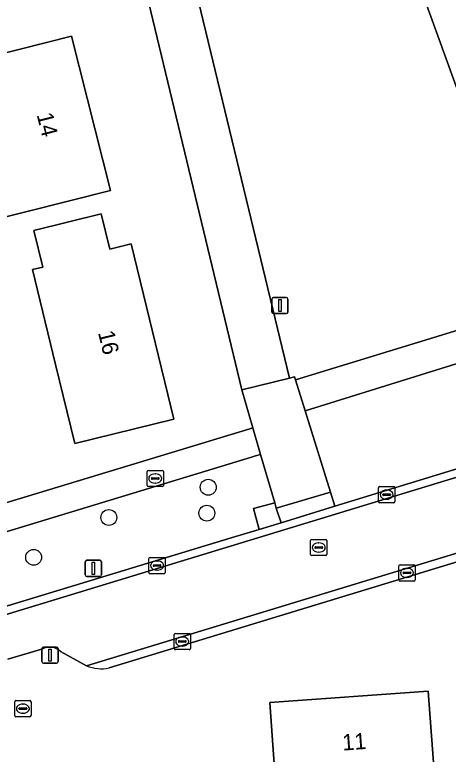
# Model space of a CAD drawing. Extents: x 162661 to 163484, y 380247 to 381230.
# Drawn here: x 162957.31 to 162984.01, y 380756.11 to 380801.65 of the extents above; entities that cross this region are included whole.
import ezdxf

# ---------------------------------------------------------------- set-up
doc = ezdxf.new("R2010")
doc.units = 0
for name, color, linetype in [('IMGEO_Afsluitpaal', 7, 'Continuous'), ('IMGEO_Berm_halfverhard', 7, 'Continuous'), ('IMGEO_Boom', 7, 'Continuous'), ('IMGEO_Brandkraan', 7, 'Continuous'), ('IMGEO_Erf', 7, 'Continuous'), ('IMGEO_Groenvoorziening', 7, 'Continuous'), ('IMGEO_Kolk', 7, 'Continuous'), ('IMGEO_Lichtmast', 7, 'Continuous'), ('IMGEO_Pand', 7, 'Continuous'), ('IMGEO_Pand_nummerreeks', 7, 'Continuous'), ('IMGEO_Parkeervlak_open', 7, 'Continuous'), ('IMGEO_Rijbaan_lokaal_gesloten', 7, 'Continuous'), ('IMGEO_Rijbaan_lokaal_open', 7, 'Continuous'), ('IMGEO_Rioolput', 7, 'Continuous'), ('IMGEO_Voetpad_open', 7, 'Continuous')]:
    doc.layers.add(name, color=color, linetype=linetype)

msp = doc.modelspace()

# ---------------------------------------------------------------- linework, layer by layer
at = {"layer": 'IMGEO_Afsluitpaal'}
for p, q in [((162958.981, 380761.814), (162958.981, 380762.614)), ((162958.981, 380762.614), (162958.981, 380761.814)), ((162959.081, 380762.714), (162959.871, 380762.714)), ((162959.871, 380762.714), (162959.081, 380762.714)), ((162959.971, 380762.614), (162959.971, 380761.814)), ((162959.971, 380761.814), (162959.971, 380762.614)), ((162959.871, 380761.714), (162959.081, 380761.714)), ((162959.081, 380761.714), (162959.871, 380761.714))]:
    msp.add_line(p, q, dxfattribs=at)
msp.add_lwpolyline([(162959.401, 380762.589), (162959.551, 380762.589), (162959.551, 380761.839), (162959.401, 380761.839), (162959.401, 380762.589)], dxfattribs=at)
for centre, start, end in [((162959.081, 380762.614), 90, 180), ((162959.081, 380762.614), 90, 180), ((162959.871, 380762.614), 0, 90), ((162959.871, 380762.614), 360, 90), ((162959.081, 380761.814), 180, 270), ((162959.081, 380761.814), 180, 270), ((162959.871, 380761.814), 270, 0), ((162959.871, 380761.814), 270, 0)]:
    msp.add_arc(centre, 0.1, start, end, dxfattribs=at)
at = {"layer": 'IMGEO_Berm_halfverhard'}
msp.add_lwpolyline([(162973.422, 380771.271), (162973.327, 380771.598), (162972.013, 380771.253), (162972.355, 380769.952), (162973.725, 380770.368)], close=True, dxfattribs=at)
at = {"layer": 'IMGEO_Boom'}
for centre in [(162969.227, 380772.553), (162963.104, 380770.691), (162969.138, 380770.958), (162958.467, 380768.237)]:
    msp.add_circle(centre, 0.489, dxfattribs=at)
at = {"layer": 'IMGEO_Brandkraan'}
for p, q in [((162965.463, 380772.667), (162965.463, 380773.519)), ((162965.538, 380773.593), (162966.39, 380773.593)), ((162966.464, 380773.519), (162966.464, 380772.667)), ((162965.722, 380773.087), (162965.722, 380773.099)), ((162966.16, 380773.05), (162965.762, 380773.05)), ((162965.765, 380773.136), (162966.163, 380773.136)), ((162965.951, 380773.373), (162965.976, 380773.373)), ((162966.206, 380773.099), (162966.206, 380773.087)), ((162966.39, 380772.593), (162965.538, 380772.593)), ((162965.974, 380772.813), (162965.949, 380772.813)), ((162957.306, 380758.494), (162957.306, 380759.346)), ((162957.381, 380759.42), (162958.233, 380759.42)), ((162958.307, 380759.346), (162958.307, 380758.494)), ((162957.565, 380758.914), (162957.565, 380758.926)), ((162958.003, 380758.877), (162957.605, 380758.877)), ((162957.608, 380758.963), (162958.006, 380758.963)), ((162957.794, 380759.2), (162957.819, 380759.2)), ((162958.049, 380758.926), (162958.049, 380758.914)), ((162958.233, 380758.42), (162957.381, 380758.42)), ((162957.817, 380758.64), (162957.792, 380758.64))]:
    msp.add_line(p, q, dxfattribs=at)
for points in [[(162965.463, 380772.667), (162965.463, 380773.519)], [(162965.538, 380773.593), (162966.39, 380773.593)], [(162966.464, 380773.519), (162966.464, 380772.667)], [(162966.39, 380772.593), (162965.538, 380772.593)], [(162957.306, 380758.494), (162957.306, 380759.346)], [(162957.381, 380759.42), (162958.233, 380759.42)], [(162958.307, 380759.346), (162958.307, 380758.494)], [(162958.233, 380758.42), (162957.381, 380758.42)]]:
    msp.add_lwpolyline(points, dxfattribs=at)
for centre, radius, start, end in [((162965.54, 380773.517), 0.0765, 91.552, 178.448), ((162965.54, 380773.517), 0.0765, 91.552, 178.448), ((162966.388, 380773.517), 0.0765, 1.552, 88.448), ((162966.388, 380773.517), 0.0765, 1.552, 88.448), ((162965.762, 380773.096), 0.0403, 85.8775, 175.7526), ((162965.759, 380773.086), 0.0366, 178.938, 274.7102), ((162966.163, 380773.093), 0.043, 264.8664, 352.4533), ((162966.167, 380773.098), 0.0386, 1.7309, 96.639), ((162965.54, 380772.669), 0.0765, 181.552, 268.448), ((162965.54, 380772.669), 0.0765, 181.552, 268.448), ((162966.388, 380772.669), 0.0765, 271.552, 358.448), ((162966.388, 380772.669), 0.0765, 271.552, 358.448), ((162957.383, 380759.344), 0.0765, 91.552, 178.448), ((162957.383, 380759.344), 0.0765, 91.552, 178.448), ((162958.231, 380759.344), 0.0765, 1.552, 88.448), ((162958.231, 380759.344), 0.0765, 1.552, 88.448), ((162957.605, 380758.923), 0.0403, 85.8775, 175.7526), ((162957.602, 380758.913), 0.0366, 178.938, 274.7102), ((162958.006, 380758.92), 0.043, 264.8664, 352.4533), ((162958.01, 380758.925), 0.0386, 1.7309, 96.639), ((162957.383, 380758.496), 0.0765, 181.552, 268.448), ((162957.383, 380758.496), 0.0765, 181.552, 268.448), ((162958.231, 380758.496), 0.0765, 271.552, 358.448), ((162958.231, 380758.496), 0.0765, 271.552, 358.448)]:
    msp.add_arc(centre, radius, start, end, dxfattribs=at)
for centre, major_axis, ratio, start_param, end_param in [((162965.95, 380773.093), (-0.387, 0.002), 0.722429, 4.712389, 7.853982), ((162965.975, 380773.093), (-0.39, 0.002), 0.717154, 1.570796, 4.712389), ((162957.793, 380758.92), (-0.387, 0.002), 0.722429, 4.712389, 7.853982), ((162957.818, 380758.92), (-0.39, 0.002), 0.717154, 1.570796, 4.712389)]:
    msp.add_ellipse(centre, major_axis=major_axis, ratio=ratio, start_param=start_param, end_param=end_param, dxfattribs=at)
at = {"layer": 'IMGEO_Erf'}
for points in [[(162926.406, 380762.393), (162971.79, 380776.161), (162971.978, 380776.218), (162971.296, 380778.555), (162965.296, 380803.494), (162959.948, 380825.491), (162975.656, 380830.504), (162983.99, 380807.505), (162992.18, 380784.912), (162992.937, 380782.334), (163021.239, 380791.885)], [(163011.662, 380776.211), (162963.124, 380761.423)], [(162959.041, 380762.599), (162956.873, 380761.967)], [(162961.731, 380761.565), (162960.12, 380762.434)]]:
    msp.add_lwpolyline(points, dxfattribs=at)
for points in [[(162954.038, 380794.474), (162952.195, 380794.009), (162951.21, 380797.917), (162960.809, 380800.338), (162963.206, 380790.836), (162955.449, 380788.879)], [(162959.03, 380786.114), (162958.478, 380788.375), (162962.625, 380789.387), (162963.154, 380787.221), (162964.474, 380787.543), (162967.111, 380776.747), (162961.004, 380775.256), (162959.817, 380780.114), (162958.39, 380785.958)], [(162973.731, 380749.423), (162973.689, 380750), (162973.017, 380759.297), (162982.788, 380760.004), (162983.365, 380752.025), (162977.61, 380751.608), (162977.729, 380750), (162977.75, 380749.714)]]:
    msp.add_lwpolyline(points, close=True, dxfattribs=at)
for centre, radius, start, end in [((162959.469, 380761.791), 0.915, 44.6851, 117.9264), ((162962.653, 380763.708), 2.333, 246.7185, 281.6405)]:
    msp.add_arc(centre, radius, start, end, dxfattribs=at)
at = {"layer": 'IMGEO_Groenvoorziening'}
for points in [[(162964.008, 380821.602), (162968.622, 380802.474), (162974.235, 380779.267), (162974.547, 380779.362), (162974.605, 380779.176), (162988.89, 380783.54), (162989.418, 380783.701), (162989.357, 380783.869), (162980.643, 380807.906), (162974.496, 380824.924)], [(162970.637, 380769.431), (162972.355, 380769.952), (162972.013, 380771.253), (162973.327, 380771.598), (162972.457, 380774.578), (162972.146, 380774.484), (162971.888, 380774.406), (162927.651, 380760.958), (162926.806, 380760.701), (162926.377, 380760.557), (162927.388, 380757.263), (162927.653, 380756.396), (162934.024, 380758.285), (162940.66, 380760.298)], [(162949.808, 380763.113), (162970.637, 380769.431)]]:
    msp.add_lwpolyline(points, dxfattribs=at)
at = {"layer": 'IMGEO_Kolk'}
for p, q in [((162979.721, 380771.67), (162979.721, 380772.522)), ((162979.796, 380772.596), (162980.648, 380772.596)), ((162980.722, 380772.522), (162980.722, 380771.67)), ((162979.98, 380772.09), (162979.98, 380772.102)), ((162980.023, 380772.139), (162980.421, 380772.139)), ((162980.209, 380772.376), (162980.234, 380772.376)), ((162980.464, 380772.102), (162980.464, 380772.09)), ((162980.418, 380772.053), (162980.02, 380772.053)), ((162980.232, 380771.816), (162980.207, 380771.816)), ((162980.648, 380771.596), (162979.796, 380771.596)), ((162965.572, 380767.305), (162965.572, 380768.157)), ((162965.647, 380768.231), (162966.499, 380768.231)), ((162966.06, 380768.011), (162966.085, 380768.011)), ((162966.573, 380768.157), (162966.573, 380767.305)), ((162965.831, 380767.725), (162965.831, 380767.737)), ((162966.269, 380767.688), (162965.871, 380767.688)), ((162965.874, 380767.774), (162966.272, 380767.774)), ((162966.315, 380767.737), (162966.315, 380767.725)), ((162980.972, 380766.853), (162980.972, 380767.705)), ((162981.047, 380767.779), (162981.899, 380767.779)), ((162981.46, 380767.559), (162981.485, 380767.559)), ((162981.973, 380767.705), (162981.973, 380766.853)), ((162966.499, 380767.231), (162965.647, 380767.231)), ((162966.083, 380767.451), (162966.058, 380767.451)), ((162981.231, 380767.273), (162981.231, 380767.285)), ((162981.669, 380767.236), (162981.271, 380767.236)), ((162981.274, 380767.322), (162981.672, 380767.322)), ((162981.715, 380767.285), (162981.715, 380767.273)), ((162981.899, 380766.779), (162981.047, 380766.779)), ((162981.483, 380766.999), (162981.458, 380766.999)), ((162967.125, 380762.626), (162967.125, 380763.478)), ((162967.2, 380763.552), (162968.052, 380763.552)), ((162968.126, 380763.478), (162968.126, 380762.626)), ((162967.384, 380763.046), (162967.384, 380763.058)), ((162967.822, 380763.009), (162967.424, 380763.009)), ((162967.427, 380763.095), (162967.825, 380763.095)), ((162967.613, 380763.332), (162967.638, 380763.332)), ((162967.868, 380763.058), (162967.868, 380763.046)), ((162968.052, 380762.552), (162967.2, 380762.552)), ((162967.636, 380762.772), (162967.611, 380762.772))]:
    msp.add_line(p, q, dxfattribs=at)
for points in [[(162979.721, 380771.67), (162979.721, 380772.522)], [(162979.796, 380772.596), (162980.648, 380772.596)], [(162980.722, 380772.522), (162980.722, 380771.67)], [(162980.648, 380771.596), (162979.796, 380771.596)], [(162965.572, 380767.305), (162965.572, 380768.157)], [(162965.647, 380768.231), (162966.499, 380768.231)], [(162966.573, 380768.157), (162966.573, 380767.305)], [(162980.972, 380766.853), (162980.972, 380767.705)], [(162981.047, 380767.779), (162981.899, 380767.779)], [(162981.973, 380767.705), (162981.973, 380766.853)], [(162966.499, 380767.231), (162965.647, 380767.231)], [(162981.899, 380766.779), (162981.047, 380766.779)], [(162967.125, 380762.626), (162967.125, 380763.478)], [(162967.2, 380763.552), (162968.052, 380763.552)], [(162968.126, 380763.478), (162968.126, 380762.626)], [(162968.052, 380762.552), (162967.2, 380762.552)]]:
    msp.add_lwpolyline(points, dxfattribs=at)
for centre, radius, start, end in [((162979.798, 380772.52), 0.0765, 91.552, 178.448), ((162979.798, 380772.52), 0.0765, 91.552, 178.448), ((162980.646, 380772.52), 0.0765, 1.552, 88.448), ((162980.646, 380772.52), 0.0765, 1.552, 88.448), ((162980.02, 380772.099), 0.0403, 85.8775, 175.7526), ((162980.017, 380772.089), 0.0366, 178.938, 274.7102), ((162980.421, 380772.096), 0.043, 264.8664, 352.4533), ((162980.425, 380772.101), 0.0386, 1.7309, 96.639), ((162979.798, 380771.672), 0.0765, 181.552, 268.448), ((162979.798, 380771.672), 0.0765, 181.552, 268.448), ((162980.646, 380771.672), 0.0765, 271.552, 358.448), ((162980.646, 380771.672), 0.0765, 271.552, 358.448), ((162965.649, 380768.155), 0.0765, 91.552, 178.448), ((162965.649, 380768.155), 0.0765, 91.552, 178.448), ((162966.497, 380768.155), 0.0765, 1.552, 88.448), ((162966.497, 380768.155), 0.0765, 1.552, 88.448), ((162965.871, 380767.734), 0.0403, 85.8775, 175.7526), ((162965.868, 380767.724), 0.0366, 178.938, 274.7102), ((162966.272, 380767.731), 0.043, 264.8664, 352.4533), ((162966.276, 380767.736), 0.0386, 1.7309, 96.639), ((162981.049, 380767.703), 0.0765, 91.552, 178.448), ((162981.049, 380767.703), 0.0765, 91.552, 178.448), ((162981.897, 380767.703), 0.0765, 1.552, 88.448), ((162981.897, 380767.703), 0.0765, 1.552, 88.448), ((162965.649, 380767.307), 0.0765, 181.552, 268.448), ((162965.649, 380767.307), 0.0765, 181.552, 268.448), ((162966.497, 380767.307), 0.0765, 271.552, 358.448), ((162966.497, 380767.307), 0.0765, 271.552, 358.448), ((162981.271, 380767.282), 0.0403, 85.8775, 175.7526), ((162981.268, 380767.272), 0.0366, 178.938, 274.7102), ((162981.672, 380767.279), 0.043, 264.8664, 352.4533), ((162981.676, 380767.284), 0.0386, 1.7309, 96.639), ((162981.049, 380766.855), 0.0765, 181.552, 268.448), ((162981.049, 380766.855), 0.0765, 181.552, 268.448), ((162981.897, 380766.855), 0.0765, 271.552, 358.448), ((162981.897, 380766.855), 0.0765, 271.552, 358.448), ((162967.202, 380763.476), 0.0765, 91.552, 178.448), ((162967.202, 380763.476), 0.0765, 91.552, 178.448), ((162968.05, 380763.476), 0.0765, 1.552, 88.448), ((162968.05, 380763.476), 0.0765, 1.552, 88.448), ((162967.424, 380763.055), 0.0403, 85.8775, 175.7526), ((162967.421, 380763.045), 0.0366, 178.938, 274.7102), ((162967.825, 380763.052), 0.043, 264.8664, 352.4533), ((162967.829, 380763.057), 0.0386, 1.7309, 96.639), ((162967.202, 380762.628), 0.0765, 181.552, 268.448), ((162967.202, 380762.628), 0.0765, 181.552, 268.448), ((162968.05, 380762.628), 0.0765, 271.552, 358.448), ((162968.05, 380762.628), 0.0765, 271.552, 358.448)]:
    msp.add_arc(centre, radius, start, end, dxfattribs=at)
for centre, major_axis, ratio, start_param, end_param in [((162980.208, 380772.096), (-0.387, 0.002), 0.722429, 4.712389, 7.853982), ((162980.233, 380772.096), (-0.39, 0.002), 0.717154, 1.570796, 4.712389), ((162966.059, 380767.731), (-0.387, 0.002), 0.722429, 4.712389, 7.853982), ((162966.084, 380767.731), (-0.39, 0.002), 0.717154, 1.570796, 4.712389), ((162981.459, 380767.279), (-0.387, 0.002), 0.722429, 4.712389, 7.853982), ((162981.484, 380767.279), (-0.39, 0.002), 0.717154, 1.570796, 4.712389), ((162967.612, 380763.052), (-0.387, 0.002), 0.722429, 4.712389, 7.853982), ((162967.637, 380763.052), (-0.39, 0.002), 0.717154, 1.570796, 4.712389)]:
    msp.add_ellipse(centre, major_axis=major_axis, ratio=ratio, start_param=start_param, end_param=end_param, dxfattribs=at)
at = {"layer": 'IMGEO_Lichtmast'}
for p, q in [((162973.149, 380783.344), (162973.149, 380784.144)), ((162973.149, 380784.144), (162973.149, 380783.344)), ((162973.249, 380784.244), (162974.039, 380784.244)), ((162974.039, 380784.244), (162973.249, 380784.244)), ((162974.139, 380784.144), (162974.139, 380783.344)), ((162974.139, 380783.344), (162974.139, 380784.144)), ((162974.039, 380783.244), (162973.249, 380783.244)), ((162973.249, 380783.244), (162974.039, 380783.244)), ((162961.752, 380768.057), (162962.542, 380768.057)), ((162962.542, 380768.057), (162961.752, 380768.057)), ((162961.652, 380767.157), (162961.652, 380767.957)), ((162961.652, 380767.957), (162961.652, 380767.157)), ((162962.642, 380767.957), (162962.642, 380767.157)), ((162962.642, 380767.157), (162962.642, 380767.957)), ((162962.542, 380767.057), (162961.752, 380767.057)), ((162961.752, 380767.057), (162962.542, 380767.057))]:
    msp.add_line(p, q, dxfattribs=at)
for points in [[(162973.569, 380784.119), (162973.719, 380784.119), (162973.719, 380783.369), (162973.569, 380783.369), (162973.569, 380784.119)], [(162962.072, 380767.932), (162962.222, 380767.932), (162962.222, 380767.182), (162962.072, 380767.182), (162962.072, 380767.932)]]:
    msp.add_lwpolyline(points, dxfattribs=at)
for centre, start, end in [((162973.249, 380784.144), 90, 180), ((162973.249, 380784.144), 90, 180), ((162974.039, 380784.144), 0, 90), ((162974.039, 380784.144), 360, 90), ((162973.249, 380783.344), 180, 270), ((162973.249, 380783.344), 180, 270), ((162974.039, 380783.344), 270, 0), ((162974.039, 380783.344), 270, 0), ((162961.752, 380767.957), 90, 180), ((162961.752, 380767.957), 90, 180), ((162962.542, 380767.957), 0, 90), ((162962.542, 380767.957), 360, 90), ((162961.752, 380767.157), 180, 270), ((162961.752, 380767.157), 180, 270), ((162962.542, 380767.157), 270, 0), ((162962.542, 380767.157), 270, 0)]:
    msp.add_arc(centre, 0.1, start, end, dxfattribs=at)
at = {"layer": 'IMGEO_Pand'}
for points in [[(162955.449, 380788.879), (162963.206, 380790.836), (162960.809, 380800.338), (162951.21, 380797.917), (162952.195, 380794.009), (162954.038, 380794.474)], [(162959.817, 380780.114), (162961.004, 380775.256), (162967.111, 380776.747), (162964.474, 380787.543), (162963.154, 380787.221), (162962.625, 380789.387), (162958.478, 380788.375), (162959.03, 380786.114), (162958.39, 380785.958)], [(162973.731, 380749.423), (162977.75, 380749.714), (162977.729, 380750), (162977.61, 380751.608), (162983.365, 380752.025), (162982.788, 380760.004), (162973.017, 380759.297), (162973.689, 380750)]]:
    msp.add_lwpolyline(points, close=True, dxfattribs=at)
at = {"layer": 'IMGEO_Parkeervlak_open'}
msp.add_lwpolyline([(162990.992, 380776.609), (162989.449, 380781.698), (162975.199, 380777.265), (162976.762, 380772.242), (162977.033, 380771.392), (162991.253, 380775.737)], close=True, dxfattribs=at)
at = {"layer": 'IMGEO_Rijbaan_lokaal_gesloten'}
for points in [[(163016.688, 380782.965), (162948.75, 380762.271), (162947.7, 380760.456)], [(162960.12, 380762.434), (162961.731, 380761.565), (163011.53, 380776.704)], [(162956.873, 380761.967), (162959.041, 380762.599)]]:
    msp.add_lwpolyline(points, dxfattribs=at)
msp.add_arc((162959.469, 380761.791), 0.915, 44.6851, 117.9264, dxfattribs=at)
at = {"layer": 'IMGEO_Rijbaan_lokaal_open'}
for points in [[(163017.65, 380783.769), (163016.926, 380783.534), (163016.492, 380783.398), (163016.15, 380783.294), (162995.902, 380777.131), (162994.583, 380776.73), (162991.253, 380775.737), (162977.033, 380771.392), (162973.725, 380770.368), (162972.355, 380769.952), (162970.637, 380769.431), (162949.808, 380763.113)], [(162948.75, 380762.271), (163016.688, 380782.965)], [(163011.738, 380776.78), (163011.53, 380776.704), (162961.731, 380761.565)], [(162963.124, 380761.423), (163011.662, 380776.211)]]:
    msp.add_lwpolyline(points, dxfattribs=at)
msp.add_arc((162962.653, 380763.708), 2.333, 246.7185, 281.6405, dxfattribs=at)
at = {"layer": 'IMGEO_Rioolput'}
for p, q in [((162975.611, 380769.344), (162976.463, 380769.344)), ((162975.536, 380768.418), (162975.536, 380769.27)), ((162975.838, 380768.887), (162976.236, 380768.887)), ((162976.024, 380769.124), (162976.049, 380769.124)), ((162976.537, 380769.27), (162976.537, 380768.418)), ((162975.795, 380768.838), (162975.795, 380768.85)), ((162976.233, 380768.801), (162975.835, 380768.801)), ((162976.047, 380768.564), (162976.022, 380768.564)), ((162976.279, 380768.85), (162976.279, 380768.838)), ((162976.463, 380768.344), (162975.611, 380768.344))]:
    msp.add_line(p, q, dxfattribs=at)
for points in [[(162975.611, 380769.344), (162976.463, 380769.344)], [(162975.536, 380768.418), (162975.536, 380769.27)], [(162976.537, 380769.27), (162976.537, 380768.418)], [(162976.463, 380768.344), (162975.611, 380768.344)]]:
    msp.add_lwpolyline(points, dxfattribs=at)
for centre, radius, start, end in [((162975.613, 380769.268), 0.0765, 91.552, 178.448), ((162975.613, 380769.268), 0.0765, 91.552, 178.448), ((162976.461, 380769.268), 0.0765, 1.552, 88.448), ((162976.461, 380769.268), 0.0765, 1.552, 88.448), ((162975.835, 380768.847), 0.0403, 85.8775, 175.7526), ((162976.24, 380768.849), 0.0386, 1.7309, 96.639), ((162975.832, 380768.837), 0.0366, 178.938, 274.7102), ((162976.236, 380768.844), 0.043, 264.8664, 352.4533), ((162975.613, 380768.42), 0.0765, 181.552, 268.448), ((162975.613, 380768.42), 0.0765, 181.552, 268.448), ((162976.461, 380768.42), 0.0765, 271.552, 358.448), ((162976.461, 380768.42), 0.0765, 271.552, 358.448)]:
    msp.add_arc(centre, radius, start, end, dxfattribs=at)
for centre, major_axis, ratio, start_param, end_param in [((162976.023, 380768.844), (-0.387, 0.002), 0.722429, 4.712389, 7.853982), ((162976.048, 380768.844), (-0.39, 0.002), 0.717154, 1.570796, 4.712389)]:
    msp.add_ellipse(centre, major_axis=major_axis, ratio=ratio, start_param=start_param, end_param=end_param, dxfattribs=at)
at = {"layer": 'IMGEO_Voetpad_open'}
msp.add_lwpolyline([(162974.496, 380824.924), (162980.643, 380807.906), (162989.357, 380783.869), (162989.418, 380783.701), (162992.18, 380784.912), (162983.99, 380807.505), (162975.656, 380830.504), (162959.948, 380825.491), (162965.296, 380803.494), (162971.296, 380778.555), (162974.235, 380779.267), (162968.622, 380802.474), (162964.008, 380821.602)], dxfattribs=at)
for points in [[(162989.449, 380781.698), (162988.89, 380783.54), (162974.605, 380779.176), (162975.199, 380777.265)], [(162975.199, 380777.265), (162974.605, 380779.176), (162974.547, 380779.362), (162974.235, 380779.267), (162971.296, 380778.555), (162971.978, 380776.218), (162972.457, 380774.578), (162973.327, 380771.598), (162973.422, 380771.271), (162976.762, 380772.242)], [(162971.978, 380776.218), (162971.79, 380776.161), (162926.406, 380762.393), (162926.02, 380762.276), (162925.869, 380762.226), (162926.377, 380760.557), (162926.806, 380760.701), (162927.651, 380760.958), (162971.888, 380774.406), (162972.146, 380774.484), (162972.457, 380774.578)], [(162973.422, 380771.271), (162973.725, 380770.368), (162977.033, 380771.392), (162976.762, 380772.242)]]:
    msp.add_lwpolyline(points, close=True, dxfattribs=at)

# ---------------------------------------------------------------- texts
at = {"layer": 'IMGEO_Pand_nummerreeks'}
for s, rotation, p in [('14', 284.1582, (162958.648, 380795.498)), ('16', 283.7261, (162962.431, 380782.081)), ('11', 4.1385, (162977.52, 380756.334))]:
    msp.add_text(s, height=1, rotation=rotation, dxfattribs=at).set_placement(p)

doc.saveas('drawing.dxf')
